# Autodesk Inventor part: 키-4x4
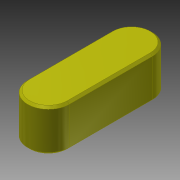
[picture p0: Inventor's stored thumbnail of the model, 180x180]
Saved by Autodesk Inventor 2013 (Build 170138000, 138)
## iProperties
Created: 2015-12
Part Number: 키-4x4
Document SubType Name: Modeling
Designer: mdu
Density: 7.86 g/cm^3
Material: 강철, 연강
Mass: 1.34709 g
Surface Area: 1.86014 cm^2
Volume: 0.171386 cm^3
Author: mdu
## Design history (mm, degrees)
sketch "스케치1"
  geometry: L1 (-2, -10)-(-2, -2) reference; L2 (2, -2)-(2, -10) reference; A1 r 2 centre (0, -2) between (2, -2) and (-2, -2) reference; A2 r 2 centre (0, -10) between (-2, -10) and (2, -10) reference; 1 further point
extrude "돌출1" new body sketch "스케치1" distance "d0" = 4; taper "d1" = 0 deg
chamfer "모따기1" distance "d2" = 0.5; stored, may be unused: second distance "d3" = 2, angle "d4" = 45 deg
node "솔리드1"
node "참조1"
